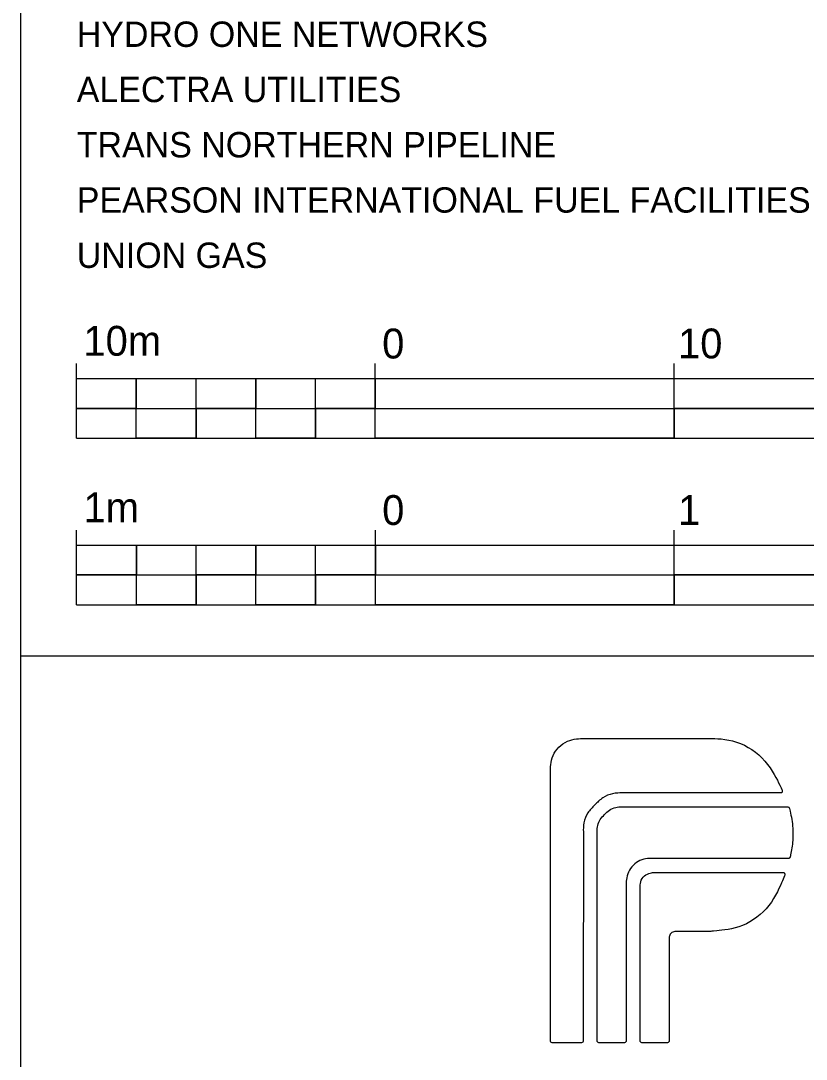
# Model space of a CAD drawing. Extents: x 613360 to 613780, y 4825621 to 4825911.
# Drawn here: x 613710.78 to 613737.07, y 4825658.01 to 4825692.78 of the extents above; entities that cross this region are included whole.
import ezdxf

# ---------------------------------------------------------------- set-up
doc = ezdxf.new("R2010")
doc.units = 0
for name, color, linetype in [('G-ANNO-BAR', 7, 'Continuous'), ('G-ANNO-TEXT', 7, 'Continuous'), ('G-TTLB-LOGO', 7, 'Continuous'), ('G-TTLB-OTLN', 7, 'Continuous')]:
    doc.layers.add(name, color=color, linetype=linetype)

msp = doc.modelspace()

# ---------------------------------------------------------------- linework, layer by layer
at = {"layer": 'G-ANNO-BAR'}
for p, q in [((613712.645, 4825678.805), (613712.645, 4825681.305)), ((613722.645, 4825678.805), (613722.645, 4825681.305)), ((613732.645, 4825678.805), (613732.645, 4825681.305)), ((613712.645, 4825680.805), (613752.645, 4825680.805)), ((613714.645, 4825678.805), (613714.645, 4825680.805)), ((613716.645, 4825678.805), (613716.645, 4825680.805)), ((613718.645, 4825678.805), (613718.645, 4825680.805)), ((613720.645, 4825678.805), (613720.645, 4825680.805)), ((613712.645, 4825679.805), (613752.645, 4825679.805)), ((613712.645, 4825678.805), (613752.645, 4825678.805)), ((613712.646, 4825673.229), (613712.646, 4825675.729)), ((613722.646, 4825673.229), (613722.646, 4825675.729)), ((613732.646, 4825673.229), (613732.646, 4825675.729)), ((613712.646, 4825675.229), (613752.646, 4825675.229)), ((613714.646, 4825673.229), (613714.646, 4825675.229)), ((613716.646, 4825673.229), (613716.646, 4825675.229)), ((613718.646, 4825673.229), (613718.646, 4825675.229)), ((613720.646, 4825673.229), (613720.646, 4825675.229)), ((613712.646, 4825674.229), (613752.646, 4825674.229)), ((613712.646, 4825673.229), (613752.646, 4825673.229))]:
    msp.add_line(p, q, dxfattribs=at)
for points in [[(613712.645, 4825680.805), (613714.645, 4825680.805), (613714.645, 4825679.805), (613712.645, 4825679.805)], [(613716.645, 4825680.805), (613718.645, 4825680.805), (613718.645, 4825679.805), (613716.645, 4825679.805)], [(613720.645, 4825680.805), (613722.645, 4825680.805), (613722.645, 4825679.805), (613720.645, 4825679.805)], [(613732.645, 4825680.805), (613742.645, 4825680.805), (613742.645, 4825679.805), (613732.645, 4825679.805)], [(613714.645, 4825679.805), (613716.645, 4825679.805), (613716.645, 4825678.805), (613714.645, 4825678.805)], [(613718.645, 4825679.805), (613720.645, 4825679.805), (613720.645, 4825678.805), (613718.645, 4825678.805)], [(613722.645, 4825679.805), (613732.645, 4825679.805), (613732.645, 4825678.805), (613722.645, 4825678.805)], [(613712.646, 4825675.229), (613714.646, 4825675.229), (613714.646, 4825674.229), (613712.646, 4825674.229)], [(613716.646, 4825675.229), (613718.646, 4825675.229), (613718.646, 4825674.229), (613716.646, 4825674.229)], [(613720.646, 4825675.229), (613722.646, 4825675.229), (613722.646, 4825674.229), (613720.646, 4825674.229)], [(613732.646, 4825675.229), (613742.646, 4825675.229), (613742.646, 4825674.229), (613732.646, 4825674.229)], [(613714.646, 4825674.229), (613716.646, 4825674.229), (613716.646, 4825673.229), (613714.646, 4825673.229)], [(613718.646, 4825674.229), (613720.646, 4825674.229), (613720.646, 4825673.229), (613718.646, 4825673.229)], [(613722.646, 4825674.229), (613732.646, 4825674.229), (613732.646, 4825673.229), (613722.646, 4825673.229)]]:
    msp.add_lwpolyline(points, close=True, dxfattribs=at)
at = {"layer": 'G-TTLB-LOGO'}
for points in [[(613736.212, 4825666.929), (613736.237, 4825666.929), (613736.269, 4825666.956), (613736.269, 4825666.991), (613736.268, 4825667.006), (613736.262, 4825667.023), (613736.261, 4825667.026), (613735.778, 4825668.05), (613734.747, 4825668.752), (613733.665, 4825668.752), (613733.665, 4825668.752), (613729.727, 4825668.752), (613729.727, 4825668.752), (613729.053, 4825668.752), (613728.504, 4825668.203), (613728.504, 4825667.529), (613728.504, 4825667.529), (613728.504, 4825658.65), (613728.504, 4825658.65), (613728.504, 4825658.604), (613728.542, 4825658.567), (613728.588, 4825658.567), (613728.588, 4825658.567), (613729.524, 4825658.567), (613729.524, 4825658.567), (613729.57, 4825658.567), (613729.607, 4825658.604), (613729.607, 4825658.65), (613729.607, 4825658.65), (613729.609, 4825665.583), (613729.609, 4825665.583), (613729.605, 4825665.938), (613729.741, 4825666.276), (613729.992, 4825666.53), (613730.246, 4825666.787), (613730.585, 4825666.929), (613730.946, 4825666.929), (613730.946, 4825666.929), (613736.212, 4825666.929), (613736.212, 4825666.929)], [(613736.212, 4825666.929), (613736.237, 4825666.929), (613736.269, 4825666.956), (613736.269, 4825666.991), (613736.268, 4825667.006), (613736.262, 4825667.023), (613736.261, 4825667.026), (613735.778, 4825668.05), (613734.747, 4825668.752), (613733.665, 4825668.752), (613733.665, 4825668.752), (613729.727, 4825668.752), (613729.727, 4825668.752), (613729.053, 4825668.752), (613728.504, 4825668.203), (613728.504, 4825667.529), (613728.504, 4825667.529), (613728.504, 4825658.65), (613728.504, 4825658.65), (613728.504, 4825658.604), (613728.542, 4825658.567), (613728.588, 4825658.567), (613728.588, 4825658.567), (613729.524, 4825658.567), (613729.524, 4825658.567), (613729.57, 4825658.567), (613729.607, 4825658.604), (613729.607, 4825658.65), (613729.607, 4825658.65), (613729.609, 4825665.583), (613729.609, 4825665.583), (613729.605, 4825665.938), (613729.741, 4825666.276), (613729.992, 4825666.53), (613730.246, 4825666.787), (613730.585, 4825666.929), (613730.946, 4825666.929), (613730.946, 4825666.929), (613736.212, 4825666.929), (613736.212, 4825666.929)], [(613736.487, 4825666.446), (613736.475, 4825666.46), (613736.459, 4825666.469), (613736.439, 4825666.469), (613736.438, 4825666.469), (613730.915, 4825666.469), (613730.915, 4825666.469), (613730.688, 4825666.461), (613730.477, 4825666.37), (613730.318, 4825666.209), (613730.162, 4825666.051), (613730.075, 4825665.846), (613730.068, 4825665.626), (613730.068, 4825665.626), (613730.068, 4825658.65), (613730.068, 4825658.65), (613730.068, 4825658.604), (613730.106, 4825658.567), (613730.152, 4825658.567), (613730.152, 4825658.567), (613730.96, 4825658.567), (613730.96, 4825658.567), (613731.006, 4825658.567), (613731.043, 4825658.604), (613731.043, 4825658.65), (613731.043, 4825658.65), (613731.043, 4825663.75), (613731.043, 4825663.75), (613731.043, 4825664.296), (613731.487, 4825664.74), (613732.033, 4825664.74), (613732.033, 4825664.74), (613736.471, 4825664.74), (613736.471, 4825664.74), (613736.498, 4825664.741), (613736.523, 4825664.761), (613736.529, 4825664.786), (613736.53, 4825664.788), (613736.53, 4825664.788), (613736.53, 4825664.79), (613736.577, 4825665.02), (613736.619, 4825665.283), (613736.619, 4825665.52), (613736.619, 4825665.821), (613736.58, 4825666.118), (613736.506, 4825666.405), (613736.5, 4825666.431), (613736.493, 4825666.44), (613736.487, 4825666.446)], [(613736.487, 4825666.446), (613736.475, 4825666.46), (613736.459, 4825666.469), (613736.439, 4825666.469), (613736.438, 4825666.469), (613730.915, 4825666.469), (613730.915, 4825666.469), (613730.688, 4825666.461), (613730.477, 4825666.37), (613730.318, 4825666.209), (613730.162, 4825666.051), (613730.075, 4825665.846), (613730.068, 4825665.626), (613730.068, 4825665.626), (613730.068, 4825658.65), (613730.068, 4825658.65), (613730.068, 4825658.604), (613730.106, 4825658.567), (613730.152, 4825658.567), (613730.152, 4825658.567), (613730.96, 4825658.567), (613730.96, 4825658.567), (613731.006, 4825658.567), (613731.043, 4825658.604), (613731.043, 4825658.65), (613731.043, 4825658.65), (613731.043, 4825663.75), (613731.043, 4825663.75), (613731.043, 4825664.296), (613731.487, 4825664.74), (613732.033, 4825664.74), (613732.033, 4825664.74), (613736.471, 4825664.74), (613736.471, 4825664.74), (613736.498, 4825664.741), (613736.523, 4825664.761), (613736.529, 4825664.786), (613736.53, 4825664.788), (613736.53, 4825664.788), (613736.53, 4825664.79), (613736.577, 4825665.02), (613736.619, 4825665.283), (613736.619, 4825665.52), (613736.619, 4825665.821), (613736.58, 4825666.118), (613736.506, 4825666.405), (613736.5, 4825666.431), (613736.493, 4825666.44), (613736.487, 4825666.446)], [(613736.288, 4825664.271), (613736.288, 4825664.271), (613732.028, 4825664.271), (613732.006, 4825664.271), (613731.983, 4825664.271), (613731.937, 4825664.267), (613731.921, 4825664.263), (613731.694, 4825664.215), (613731.521, 4825664.017), (613731.508, 4825663.779), (613731.508, 4825663.779), (613731.508, 4825658.65), (613731.508, 4825658.65), (613731.508, 4825658.604), (613731.545, 4825658.567), (613731.592, 4825658.567), (613731.592, 4825658.567), (613732.399, 4825658.567), (613732.399, 4825658.567), (613732.445, 4825658.567), (613732.483, 4825658.604), (613732.483, 4825658.65), (613732.483, 4825658.65), (613732.483, 4825662.035), (613732.483, 4825662.035), (613732.483, 4825662.177), (613732.597, 4825662.291), (613732.739, 4825662.291), (613732.739, 4825662.291), (613733.732, 4825662.291), (613733.732, 4825662.291), (613733.732, 4825662.291), (613733.871, 4825662.295), (613733.907, 4825662.299), (613734.96, 4825662.394), (613735.901, 4825663.105), (613736.347, 4825664.166), (613736.356, 4825664.186), (613736.357, 4825664.217), (613736.348, 4825664.236), (613736.335, 4825664.261), (613736.314, 4825664.271), (613736.288, 4825664.271)], [(613736.288, 4825664.271), (613736.288, 4825664.271), (613732.028, 4825664.271), (613732.006, 4825664.271), (613731.983, 4825664.271), (613731.937, 4825664.267), (613731.921, 4825664.263), (613731.694, 4825664.215), (613731.521, 4825664.017), (613731.508, 4825663.779), (613731.508, 4825663.779), (613731.508, 4825658.65), (613731.508, 4825658.65), (613731.508, 4825658.604), (613731.545, 4825658.567), (613731.592, 4825658.567), (613731.592, 4825658.567), (613732.399, 4825658.567), (613732.399, 4825658.567), (613732.445, 4825658.567), (613732.483, 4825658.604), (613732.483, 4825658.65), (613732.483, 4825658.65), (613732.483, 4825662.035), (613732.483, 4825662.035), (613732.483, 4825662.177), (613732.597, 4825662.291), (613732.739, 4825662.291), (613732.739, 4825662.291), (613733.732, 4825662.291), (613733.732, 4825662.291), (613733.732, 4825662.291), (613733.871, 4825662.295), (613733.907, 4825662.299), (613734.96, 4825662.394), (613735.901, 4825663.105), (613736.347, 4825664.166), (613736.356, 4825664.186), (613736.357, 4825664.217), (613736.348, 4825664.236), (613736.335, 4825664.261), (613736.314, 4825664.271), (613736.288, 4825664.271)]]:
    msp.add_open_spline(points, degree=3, dxfattribs=at)
at = {"layer": 'G-TTLB-OTLN'}
for p, q in [((613710.777, 4825623.508), (613710.777, 4825815.929)), ((613774.178, 4825671.507), (613710.777, 4825671.507))]:
    msp.add_line(p, q, dxfattribs=at)

# ---------------------------------------------------------------- texts
at = {"layer": 'G-ANNO-BAR'}
msp.add_text('10m', height=1, dxfattribs=at).set_placement((613712.873, 4825681.569))
for s, p in [('0', (613722.874, 4825681.478)), ('10', (613732.777, 4825681.48)), ('1m', (613712.876, 4825675.992)), ('0', (613722.874, 4825675.903)), ('1', (613732.778, 4825675.902))]:
    msp.add_text(s, height=1, rotation=360, dxfattribs=at).set_placement(p)
at = {"layer": 'G-ANNO-TEXT'}
for s, p in [('HYDRO ONE NETWORKS', (613712.651, 4825691.91)), ('ALECTRA UTILITIES', (613712.651, 4825690.06)), ('TRANS NORTHERN PIPELINE', (613712.651, 4825688.21)), ('PEARSON INTERNATIONAL FUEL FACILITIES CORP.', (613712.651, 4825686.36)), ('UNION GAS', (613712.651, 4825684.51))]:
    msp.add_text(s, height=0.85, dxfattribs=at).set_placement(p)

doc.saveas('drawing.dxf')
